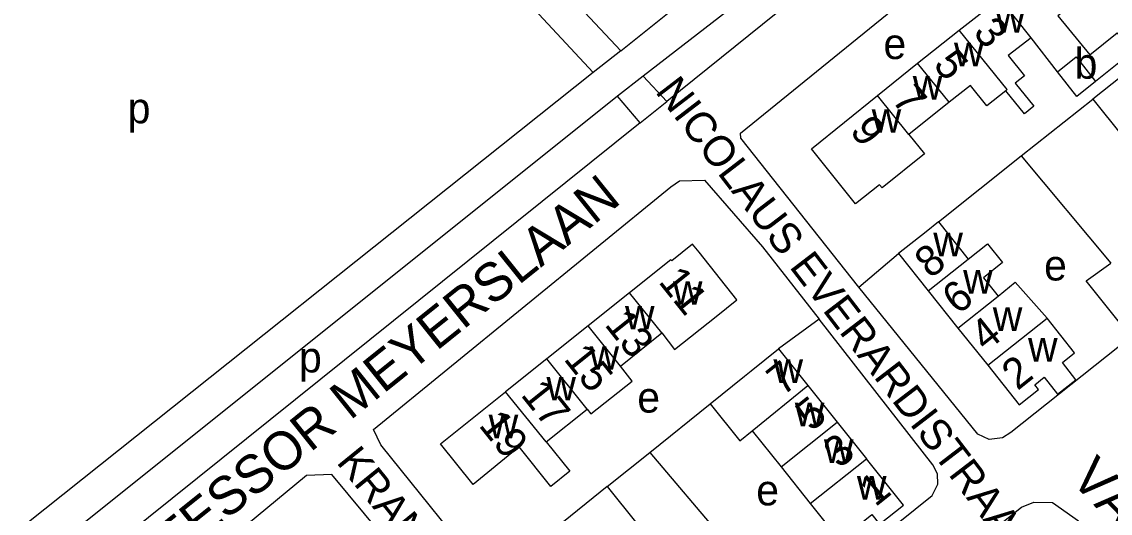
# Model space of a CAD drawing. Extents: x 157569 to 159501, y 382907 to 384670.
# Drawn here: x 158181 to 158323.4, y 384049.2 to 384113.4 of the extents above; entities that cross this region are included whole.
import ezdxf

# ---------------------------------------------------------------- set-up
doc = ezdxf.new("R2010")
doc.units = 0
for name, color, linetype in [('BLT_Basislijn', 7, 'Continuous'), ('BLT_Bebouwing', 7, 'Continuous'), ('BLT_Centroide', 7, 'Continuous'), ('BLT_Huisnummer', 7, 'Continuous'), ('BLT_Huisnummer_ tussenligend', 7, 'Continuous'), ('BLT_Onderverdeling_panden', 7, 'Continuous'), ('BLT_Straatnaam', 7, 'Continuous'), ('BLT_Straatnaam_verkleind', 7, 'Continuous')]:
    doc.layers.add(name, color=color, linetype=linetype)

msp = doc.modelspace()

# ---------------------------------------------------------------- linework, layer by layer
at = {"layer": 'BLT_Basislijn'}
for p, q in [((158259.34, 384109.64), (158290.59, 384134.73)), ((158293.59, 384130.73), (158262.27, 384106.32)), ((158259.34, 384109.64), (158255.74, 384106.79)), ((158255.74, 384106.79), (158159.63, 384030.35)), ((158262.27, 384106.32), (158258.91, 384103.7)), ((158265.35, 384103.04), (158262.27, 384106.32)), ((158258.91, 384103.7), (158162.87, 384026.97)), ((158261.86, 384100.23), (158258.91, 384103.7)), ((158261.86, 384100.23), (158265.35, 384103.04)), ((158311.71, 384095.9), (158321.09, 384103.34)), ((158261.86, 384100.23), (158164.82, 384022.41)), ((158300.89, 384087.3), (158311.71, 384095.9)), ((158311.71, 384095.9), (158323.44, 384081.9)), ((158290.49, 384078.75), (158295.67, 384083.13)), ((158285.27, 384074.55), (158279.99, 384070.67)), ((158263.12, 384057.14), (158271.03, 384063.51)), ((158257.57, 384052.67), (158263.12, 384057.14)), ((158263.12, 384057.14), (158275.06, 384043.13))]:
    msp.add_line(p, q, dxfattribs=at)
for points in [[(158259.34, 384109.64), (158224.88, 384146.34), (158221.05, 384150.49), (158220.98, 384150.94), (158235.41, 384164.89), (158256.15, 384184.11)], [(158300.62, 384166.5), (158309.49, 384145.27), (158309.97, 384143.83), (158310.2, 384140.57), (158309.56, 384139.29), (158306.71, 384136.32), (158265.35, 384103.04)], [(158255.74, 384106.79), (158217.81, 384147.57), (158215.9, 384147.14), (158200.72, 384163.57), (158199.22, 384164.34), (158111.6, 384082.82), (158111.53, 384081.84)], [(158290.49, 384078.75), (158275.04, 384098.24), (158274.99, 384098.88), (158314.05, 384130.59)], [(158242.22, 384040.44), (158227.94, 384058.12), (158226.98, 384060.14), (158265.89, 384091.86), (158267.01, 384092.66), (158270.27, 384092.72), (158277.89, 384084), (158285.27, 384074.55)], [(158326.05, 384072.22), (158310.35, 384059.73), (158309.26, 384059.07), (158307.52, 384058.85), (158306.06, 384059.52), (158290.49, 384078.75)], [(158283.83, 384038.48), (158300.07, 384051.51), (158300.79, 384052.99), (158300.76, 384054.33), (158300.16, 384055.54), (158285.27, 384074.55)], [(158236.72, 384035.99), (158221.56, 384054.26), (158218.23, 384054.13), (158179, 384021.66), (158179.05, 384021.18), (158193.93, 384001.52)], [(158313.38, 383952.33), (158263.33, 384004.09), (158262.44, 384005.41), (158262.02, 384007.24), (158262.28, 384009.01), (158263.7, 384011.59), (158311.75, 384050), (158313.38, 384050.62), (158315.83, 384050.59), (158319.23, 384048.21)]]:
    msp.add_lwpolyline(points, dxfattribs=at)
at = {"layer": 'BLT_Bebouwing'}
for p, q in [((158303.59, 384112.34), (158308.9, 384116.55)), ((158298.17, 384108.01), (158303.59, 384112.34)), ((158292.93, 384103.82), (158298.17, 384108.01)), ((158302.28, 384102.94), (158297.03, 384098.69)), ((158321.09, 384103.34), (158324.98, 384098.47)), ((158300.89, 384087.3), (158304.79, 384082.43)), ((158295.67, 384083.13), (158299.55, 384078.26)), ((158299.55, 384078.26), (158303.44, 384073.4)), ((158260.5, 384078), (158255.09, 384073.69)), ((158255.09, 384073.69), (158249.68, 384069.37)), ((158259.28, 384068.44), (158264.69, 384072.76)), ((158303.44, 384073.4), (158307.33, 384068.53)), ((158279.99, 384070.67), (158283.81, 384065.88)), ((158249.68, 384069.37), (158244.27, 384065.05)), ((158283.81, 384065.88), (158287.64, 384061.09)), ((158249.6, 384058.54), (158254.94, 384062.8)), ((158287.64, 384061.09), (158291.47, 384056.3)), ((158276.53, 384059.97), (158280.3, 384055.25)), ((158280.3, 384055.25), (158284.11, 384050.48))]:
    msp.add_line(p, q, dxfattribs=at)
for points in [[(158308.9, 384116.55), (158314.25, 384120.87), (158315.67, 384119.08), (158317.04, 384119.79), (158318.07, 384119.68), (158318.89, 384119.06), (158319.31, 384118.1), (158319.21, 384117.08), (158318.59, 384116.24), (158318.2, 384115.9), (158318.37, 384115.71), (158316.51, 384114.23), (158320.69, 384109.14), (158324.26, 384112), (158326.23, 384109.48), (158321.43, 384105.62)], [(158313, 384111.35), (158310.03, 384109.02), (158312.15, 384106.37), (158310.94, 384105.41), (158313.35, 384102.4), (158312.13, 384101.42), (158309.72, 384104.43)], [(158316.48, 384106.9), (158313, 384111.35)], [(158328.48, 384109.24), (158324.86, 384106.35), (158321.09, 384103.34)], [(158321.43, 384105.62), (158319, 384103.66), (158316.48, 384106.9)], [(158297.03, 384098.69), (158299.05, 384096.17), (158293.51, 384091.73), (158293.19, 384092.13), (158290.06, 384089.63), (158284.29, 384096.84), (158292.93, 384103.82)], [(158309.72, 384104.43), (158307.23, 384102.44), (158305.1, 384105.12), (158302.28, 384102.94)], [(158300.89, 384087.3), (158299.27, 384086), (158295.67, 384083.13)], [(158264.69, 384072.76), (158266.38, 384070.6), (158271.81, 384074.93), (158274.54, 384077.11), (158269.59, 384083.32), (158268.74, 384084.38), (158266.01, 384082.19), (158265.9, 384082.32), (158260.5, 384078)], [(158304.79, 384082.43), (158307.32, 384084.43), (158309.28, 384081.97), (158306.79, 384079.98), (158308.68, 384077.56)], [(158324.74, 384073.92), (158320.23, 384079.56), (158323.44, 384081.9)], [(158308.68, 384077.56), (158310.91, 384079.4), (158315.09, 384074.7)], [(158307.33, 384068.53), (158311.46, 384063.36), (158313.98, 384065.38), (158313.48, 384066), (158314.71, 384066.98), (158316.48, 384064.76), (158318.87, 384066.65), (158317.1, 384068.89), (158318.7, 384070.18), (158315.09, 384074.7)], [(158271.03, 384063.51), (158275.51, 384067.1), (158276.4, 384067.81), (158279.99, 384070.67)], [(158254.94, 384062.8), (158255.44, 384062.18), (158260.81, 384066.47), (158259.28, 384068.44)], [(158249.6, 384058.54), (158252.68, 384054.69), (158250.2, 384052.71), (158246.06, 384057.89), (158240.04, 384052.93), (158235.77, 384058.27), (158244.27, 384065.05)], [(158271.03, 384063.51), (158274.92, 384058.67), (158276.53, 384059.97)], [(158284.11, 384050.48), (158287.97, 384045.65), (158290.12, 384047.36), (158292.19, 384049.02), (158293.2, 384047.75), (158296.31, 384050.24), (158291.47, 384056.3)], [(158257.57, 384052.67), (158250.91, 384047.34), (158247.29, 384044.45)], [(158257.57, 384052.67), (158261.44, 384047.83), (158256.9, 384044.28)]]:
    msp.add_lwpolyline(points, dxfattribs=at)
at = {"layer": 'BLT_Onderverdeling_panden'}
for p, q in [((158313, 384111.35), (158308.9, 384116.55)), ((158302.28, 384102.94), (158298.17, 384108.01)), ((158297.03, 384098.69), (158292.93, 384103.82)), ((158299.55, 384078.26), (158304.79, 384082.43)), ((158264.69, 384072.76), (158260.5, 384078)), ((158303.44, 384073.4), (158308.68, 384077.56)), ((158307.33, 384068.53), (158315.09, 384074.7)), ((158259.28, 384068.44), (158255.09, 384073.69)), ((158254.94, 384062.8), (158249.68, 384069.37)), ((158276.53, 384059.97), (158283.81, 384065.88)), ((158249.6, 384058.54), (158244.27, 384065.05)), ((158280.3, 384055.25), (158287.64, 384061.09)), ((158284.11, 384050.48), (158291.47, 384056.3))]:
    msp.add_line(p, q, dxfattribs=at)
for points in [[(158309.72, 384104.43), (158309.9, 384104.57), (158303.59, 384112.34)], [(158316.48, 384106.9), (158318.9, 384108.85), (158321.43, 384105.62)]]:
    msp.add_lwpolyline(points, dxfattribs=at)

# ---------------------------------------------------------------- texts
at = {"layer": 'BLT_Centroide'}
for s, p in [('w', (158308.34, 384112)), ('e', (158293.7, 384108.57)), ('w', (158302.93, 384107.62)), ('b', (158318.7, 384106)), ('w', (158297.53, 384103.28)), ('p', (158194.84, 384100.17)), ('w', (158292.16, 384098.94)), ('w', (158300.22, 384082.78)), ('e', (158314.71, 384079.62)), ('w', (158304.12, 384077.91)), ('w', (158266.16, 384076.45)), ('w', (158259.89, 384073.22)), ('w', (158308, 384073.03)), ('w', (158255.25, 384067.95)), ('w', (158312.61, 384069.03)), ('p', (158217.25, 384067.6)), ('w', (158279.31, 384066.22)), ('w', (158249.61, 384063.95)), ('e', (158261.5, 384062.35)), ('w', (158282.11, 384060.56)), ('w', (158242.06, 384059)), ('w', (158285.91, 384055.78)), ('w', (158290.23, 384050.97)), ('e', (158277.06, 384050.22))]:
    msp.add_text(s, height=4, dxfattribs=at).set_placement(p)
at = {"layer": 'BLT_Huisnummer'}
for s, rotation, p in [('5', 308.9897, (158300.09, 384107.78)), ('9', 308.6679, (158289.18, 384099.14)), ('8', 38.5079, (158299.83, 384079.77)), ('11', 308.5919, (158264.16, 384079.44)), ('15', 308.5892, (158251.77, 384069.34)), ('2', 38.625, (158311.23, 384065.15)), ('7', 38.6328, (158280.5, 384064.42)), ('19', 308.6105, (158240.66, 384060.67)), ('1', 38.6194, (158292.62, 384049.93))]:
    msp.add_text(s, height=4, rotation=rotation, dxfattribs=at).set_placement(p)
at = {"layer": 'BLT_Huisnummer_ tussenligend'}
for s, rotation, p in [('3', 308.9897, (158305.31, 384112)), ('7', 308.9897, (158294.66, 384103.19)), ('6', 38.625, (158303.44, 384075.04)), ('13', 308.5919, (158257.11, 384073.83)), ('4', 38.625, (158307.1, 384070.21)), ('17', 308.5892, (158246.15, 384064.65)), ('5', 38.6194, (158284.25, 384059.78)), ('3', 38.6194, (158287.91, 384054.95))]:
    msp.add_text(s, height=4, rotation=rotation, dxfattribs=at).set_placement(p)
at = {"layer": 'BLT_Straatnaam'}
for s, rotation, p in [('PROFESSOR MEYERSLAAN', 38.7419, (158189.74, 384033.83)), ('VAN MAANENSTRAAT', 314.0513, (158318, 384053.53))]:
    msp.add_text(s, height=5, rotation=rotation, dxfattribs=at).set_placement(p)
at = {"layer": 'BLT_Straatnaam_verkleind'}
for s, rotation, p in [('LEENDERT DONKERSTRAAT', 308.4816, (158310.82, 384149.67)), ('NICOLAUS EVERARDISTRAAT', 307.4816, (158263.75, 384104.29)), ('KRANENBURGSTRAAT', 309.0762, (158222.04, 384055.84))]:
    msp.add_text(s, height=4, rotation=rotation, dxfattribs=at).set_placement(p)

doc.saveas('drawing.dxf')
